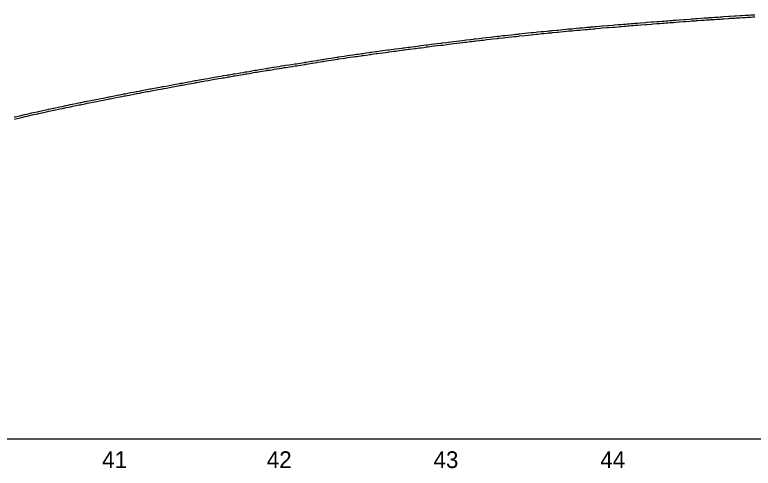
# Model space of a CAD drawing. Extents: x 2115752 to 2121174, y 562881 to 567245.
# Drawn here: x 2119738.2 to 2120180.3, y 566358.2 to 566630 of the extents above; entities that cross this region are included whole.
import ezdxf

# ---------------------------------------------------------------- set-up
doc = ezdxf.new("R2010")
doc.units = 0
for name, color, linetype in [('Exist Profile Cell', 7, 'Continuous'), ('Exist Vertical Profile Ground Line', 7, 'Continuous'), ('Exist Vertical Profile Horizontal Axis Label Major', 7, 'Continuous'), ('Scratch_Level_1', 7, 'Continuous')]:
    doc.layers.add(name, color=color, linetype=linetype)

msp = doc.modelspace()

# ---------------------------------------------------------------- linework, layer by layer
at = {"layer": 'Exist Profile Cell'}
msp.add_line((2116696.3, 566375.81), (2121174.42, 566375.81), dxfattribs=at)
at = {"layer": 'Exist Vertical Profile Ground Line'}
for points in [[(2120149.05, 566626.68), (2120150.9, 566626.82), (2120152.4, 566626.9), (2120153.55, 566626.98), (2120154.01, 566627.02), (2120154.64, 566627.07), (2120155.69, 566627.14), (2120157.12, 566627.22), (2120158.63, 566627.37), (2120159.06, 566627.39), (2120160.61, 566627.44), (2120161.62, 566627.53), (2120162.61, 566627.62), (2120165.77, 566627.83), (2120166.36, 566627.87), (2120169.24, 566628.05), (2120170.04, 566628.1), (2120172.31, 566628.24), (2120173.77, 566628.33), (2120175.64, 566628.44), (2120176.85, 566628.51), (2120177.46, 566628.54), (2120178.95, 566628.62), (2120180.06, 566628.67), (2120181.26, 566628.75)], [(2120011.63, 566614), (2120012.6, 566614.15), (2120013.46, 566614.26), (2120014.13, 566614.35), (2120016.38, 566614.59), (2120017.47, 566614.71), (2120018.78, 566614.85), (2120020.74, 566615.11), (2120022.89, 566615.36), (2120024.11, 566615.51), (2120027.23, 566615.86), (2120027.65, 566615.91), (2120028.14, 566615.95), (2120030.56, 566616.24), (2120031.93, 566616.4), (2120033.82, 566616.58), (2120035.74, 566616.78), (2120037.12, 566616.94), (2120038.3, 566617.06), (2120039.73, 566617.22), (2120040.35, 566617.28), (2120043.63, 566617.64), (2120045.58, 566617.85), (2120047.4, 566618.04), (2120048.98, 566618.17), (2120050.3, 566618.34), (2120051.33, 566618.44), (2120053.55, 566618.68), (2120055.02, 566618.82), (2120056.83, 566618.98), (2120057.78, 566619.07), (2120059.06, 566619.2), (2120059.64, 566619.23), (2120060.04, 566619.28), (2120062.87, 566619.57), (2120063.34, 566619.62), (2120066.63, 566619.94), (2120068.52, 566620.08), (2120069.9, 566620.27), (2120070.25, 566620.3), (2120070.67, 566620.34), (2120071.95, 566620.41), (2120073.16, 566620.57), (2120074.44, 566620.69), (2120076.45, 566620.86), (2120078.15, 566621.01), (2120079.73, 566621.14), (2120080.84, 566621.24), (2120082.08, 566621.36), (2120082.6, 566621.38), (2120083.03, 566621.43), (2120084.39, 566621.53), (2120085.48, 566621.65), (2120086.41, 566621.75), (2120088.42, 566621.94), (2120089.88, 566622.07), (2120093.09, 566622.33), (2120093.63, 566622.37), (2120096.24, 566622.57), (2120097.41, 566622.66), (2120099.58, 566622.84), (2120100.37, 566622.91), (2120100.71, 566622.94), (2120101.15, 566622.97), (2120102.76, 566623.08), (2120103.88, 566623.18), (2120105.16, 566623.28), (2120106.09, 566623.35), (2120107.4, 566623.46), (2120108.32, 566623.55), (2120109.48, 566623.66), (2120111.14, 566623.79), (2120112.98, 566623.93), (2120116.07, 566624.18), (2120116.66, 566624.23), (2120119.34, 566624.43), (2120120.41, 566624.51), (2120122.64, 566624.67), (2120123.55, 566624.74), (2120124.2, 566624.79), (2120125.93, 566624.92), (2120126.93, 566625.01), (2120127.98, 566625.08), (2120128.6, 566625.1), (2120129.15, 566625.17), (2120130.51, 566625.27), (2120131.17, 566625.33), (2120132.02, 566625.4), (2120132.64, 566625.44), (2120134, 566625.53), (2120135.97, 566625.74), (2120138.78, 566625.93), (2120139.18, 566625.96), (2120139.71, 566626), (2120142.5, 566626.21), (2120143.4, 566626.27), (2120144.6, 566626.32), (2120145.8, 566626.45), (2120146.4, 566626.49), (2120147.19, 566626.55), (2120149.05, 566626.68)], [(2119869.39, 566593.31), (2119870.01, 566593.41), (2119871.54, 566593.63), (2119873.3, 566594), (2119875.11, 566594.22), (2119876.49, 566594.51), (2119877.26, 566594.63), (2119878.63, 566594.82), (2119879.76, 566595.04), (2119881.2, 566595.32), (2119882.21, 566595.49), (2119883.11, 566595.65), (2119885.05, 566595.96), (2119886.4, 566596.17), (2119888.87, 566596.58), (2119889.26, 566596.64), (2119889.61, 566596.7), (2119891.05, 566596.88), (2119892.94, 566597.26), (2119893.45, 566597.34), (2119896.6, 566597.84), (2119898.1, 566598.05), (2119899.53, 566598.33), (2119900.51, 566598.48), (2119902.69, 566598.77), (2119904.29, 566599.02), (2119906.04, 566599.3), (2119907.01, 566599.43), (2119908.08, 566599.63), (2119909.29, 566599.82), (2119911.89, 566600.24), (2119912.25, 566600.3), (2119912.56, 566600.35), (2119914.12, 566600.57), (2119915.93, 566600.92), (2119916.45, 566601.01), (2119919.09, 566601.42), (2119919.73, 566601.52), (2119921.15, 566601.71), (2119922.37, 566601.94), (2119922.95, 566602.03), (2119923.66, 566602.16), (2119924.74, 566602.3), (2119925.74, 566602.48), (2119927.58, 566602.76), (2119928.92, 566602.97), (2119930, 566603.09), (2119931.28, 566603.33), (2119931.82, 566603.41), (2119932.24, 566603.48), (2119935.58, 566603.97), (2119937.66, 566604.28), (2119939.04, 566604.48), (2119940.7, 566604.68), (2119942.03, 566604.91), (2119943.01, 566605.06), (2119944.18, 566605.21), (2119945.32, 566605.4), (2119946.09, 566605.5), (2119946.95, 566605.63), (2119948.6, 566605.87), (2119950.67, 566606.16), (2119951.33, 566606.24), (2119951.87, 566606.32), (2119954.54, 566606.71), (2119955.11, 566606.79), (2119958.49, 566607.26), (2119961.65, 566607.67), (2119962.38, 566607.76), (2119965.09, 566608.12), (2119966.23, 566608.27), (2119968.25, 566608.54), (2119970.05, 566608.79), (2119970.87, 566608.88), (2119971.52, 566608.98), (2119974, 566609.32), (2119974.43, 566609.37), (2119974.78, 566609.42), (2119977.75, 566609.78), (2119978.16, 566609.83), (2119980.53, 566610.14), (2119981.52, 566610.26), (2119983.25, 566610.46), (2119984.62, 566610.68), (2119985.05, 566610.73), (2119985.5, 566610.79), (2119987.91, 566611.08), (2119989.46, 566611.28), (2119991.17, 566611.48), (2119993.19, 566611.72), (2119993.9, 566611.79), (2119994.46, 566611.87), (2119997.02, 566612.18), (2119997.77, 566612.28), (2120001.04, 566612.67), (2120004.66, 566613.12), (2120006.43, 566613.32), (2120007.63, 566613.51), (2120008.67, 566613.64), (2120010.9, 566613.91), (2120011.63, 566614)], [(2119738.06, 566567.51), (2119738.89, 566567.69), (2119742.2, 566568.45), (2119744.39, 566568.96), (2119745.64, 566569.25), (2119748.71, 566569.94), (2119749.53, 566570.12), (2119752.03, 566570.67), (2119752.68, 566570.81), (2119753.49, 566571.01), (2119754.55, 566571.22), (2119755.35, 566571.42), (2119757.27, 566571.86), (2119758.63, 566572.14), (2119759.84, 566572.38), (2119761.39, 566572.73), (2119761.83, 566572.82), (2119765.13, 566573.55), (2119766.79, 566573.86), (2119768.96, 566574.35), (2119770.44, 566574.62), (2119771.66, 566574.9), (2119772.85, 566575.17), (2119774.98, 566575.62), (2119775.71, 566575.75), (2119776.67, 566575.94), (2119777.58, 566576.09), (2119778.22, 566576.24), (2119780.41, 566576.69), (2119781.03, 566576.8), (2119781.57, 566576.92), (2119782.92, 566577.18), (2119784.82, 566577.6), (2119787.06, 566578.05), (2119788.18, 566578.27), (2119789.99, 566578.56), (2119791.37, 566578.87), (2119792.21, 566579.04), (2119794.64, 566579.51), (2119795.25, 566579.63), (2119796.04, 566579.8), (2119797.11, 566580), (2119797.96, 566580.18), (2119799.79, 566580.54), (2119801.2, 566580.82), (2119802.37, 566581.02), (2119803.79, 566581.33), (2119804.16, 566581.4), (2119804.47, 566581.46), (2119807.76, 566582.09), (2119809.47, 566582.37), (2119811.04, 566582.71), (2119811.44, 566582.79), (2119813, 566583.05), (2119814.32, 566583.32), (2119815.43, 566583.54), (2119817.49, 566583.93), (2119818.35, 566584.09), (2119819.31, 566584.28), (2119820.15, 566584.43), (2119820.87, 566584.57), (2119823.04, 566584.97), (2119824.11, 566585.18), (2119825.4, 566585.39), (2119826.81, 566585.69), (2119827.38, 566585.79), (2119828.97, 566586.06), (2119830.88, 566586.44), (2119833.84, 566586.98), (2119834.75, 566587.15), (2119837.2, 566587.6), (2119837.84, 566587.71), (2119838.59, 566587.86), (2119839.6, 566588.04), (2119840.47, 566588.21), (2119841.36, 566588.35), (2119842.52, 566588.59), (2119843.77, 566588.82), (2119846.28, 566589.27), (2119846.68, 566589.34), (2119847.01, 566589.4), (2119849.97, 566589.92), (2119850.36, 566589.99), (2119852.33, 566590.36), (2119853.89, 566590.64), (2119856.83, 566591.15), (2119857.9, 566591.33), (2119859.16, 566591.52), (2119860.12, 566591.71), (2119861.7, 566591.98), (2119862.66, 566592.13), (2119863.47, 566592.27), (2119865.54, 566592.64), (2119866.14, 566592.74), (2119866.72, 566592.84), (2119869.39, 566593.31)]]:
    msp.add_lwpolyline(points, dxfattribs=at)
at = {"layer": 'Scratch_Level_1'}
for points in [[(2120011.44, 566615.24), (2120012.43, 566615.39), (2120013.3, 566615.5), (2120013.98, 566615.59), (2120016.24, 566615.83), (2120017.33, 566615.95), (2120018.63, 566616.1), (2120020.59, 566616.35), (2120022.74, 566616.61), (2120023.97, 566616.75), (2120027.1, 566617.1), (2120027.52, 566617.15), (2120028.01, 566617.2), (2120030.41, 566617.48), (2120031.8, 566617.65), (2120033.69, 566617.83), (2120035.61, 566618.03), (2120036.98, 566618.18), (2120038.16, 566618.31), (2120039.6, 566618.46), (2120040.22, 566618.52), (2120043.5, 566618.88), (2120045.44, 566619.1), (2120047.29, 566619.29), (2120048.85, 566619.41), (2120050.15, 566619.58), (2120051.2, 566619.69), (2120053.43, 566619.92), (2120054.9, 566620.06), (2120056.71, 566620.22), (2120057.66, 566620.32), (2120058.97, 566620.44), (2120059.52, 566620.47), (2120059.89, 566620.52), (2120062.75, 566620.82), (2120063.23, 566620.86), (2120066.53, 566621.19), (2120068.39, 566621.32), (2120069.76, 566621.51), (2120070.13, 566621.55), (2120070.58, 566621.59), (2120071.83, 566621.66), (2120073.02, 566621.82), (2120074.33, 566621.93), (2120076.34, 566622.11), (2120078.04, 566622.26), (2120079.62, 566622.39), (2120080.72, 566622.49), (2120081.99, 566622.61), (2120082.5, 566622.63), (2120082.91, 566622.68), (2120084.28, 566622.78), (2120085.35, 566622.9), (2120086.29, 566622.99), (2120088.31, 566623.18), (2120089.77, 566623.31), (2120092.99, 566623.57), (2120093.54, 566623.62), (2120096.15, 566623.82), (2120097.31, 566623.91), (2120099.47, 566624.08), (2120100.27, 566624.16), (2120100.63, 566624.18), (2120101.07, 566624.21), (2120102.66, 566624.33), (2120103.77, 566624.42), (2120105.06, 566624.52), (2120105.99, 566624.6), (2120107.29, 566624.71), (2120108.2, 566624.8), (2120109.37, 566624.9), (2120111.04, 566625.04), (2120112.88, 566625.18), (2120115.97, 566625.43), (2120116.57, 566625.47), (2120119.25, 566625.68), (2120120.32, 566625.75), (2120122.54, 566625.92), (2120123.45, 566625.99), (2120124.11, 566626.04), (2120125.83, 566626.17), (2120126.83, 566626.25), (2120127.92, 566626.33), (2120128.51, 566626.35), (2120129.03, 566626.41), (2120130.41, 566626.52), (2120131.06, 566626.57), (2120131.93, 566626.64), (2120132.56, 566626.69), (2120133.9, 566626.77), (2120135.86, 566626.98), (2120138.69, 566627.18), (2120139.09, 566627.21), (2120139.62, 566627.24), (2120142.4, 566627.45), (2120143.33, 566627.52), (2120144.51, 566627.56), (2120145.69, 566627.7), (2120146.31, 566627.74), (2120147.1, 566627.8), (2120148.97, 566627.93)], [(2120148.96, 566627.93), (2120150.82, 566628.06), (2120152.32, 566628.15), (2120153.45, 566628.23), (2120153.9, 566628.26), (2120154.54, 566628.32), (2120155.61, 566628.39), (2120157.03, 566628.46), (2120158.53, 566628.61), (2120159, 566628.64), (2120160.53, 566628.69), (2120161.51, 566628.78), (2120162.51, 566628.87), (2120165.69, 566629.08), (2120166.28, 566629.12), (2120169.16, 566629.3), (2120169.96, 566629.35), (2120172.23, 566629.49), (2120173.7, 566629.58), (2120175.57, 566629.69), (2120176.79, 566629.75), (2120177.4, 566629.79), (2120178.88, 566629.86), (2120179.98, 566629.92), (2120181.21, 566630)], [(2119869.18, 566594.54), (2119869.82, 566594.65), (2119871.33, 566594.86), (2119873.09, 566595.23), (2119874.9, 566595.45), (2119876.26, 566595.74), (2119877.07, 566595.87), (2119878.43, 566596.05), (2119879.51, 566596.27), (2119880.98, 566596.56), (2119882, 566596.72), (2119882.9, 566596.88), (2119884.85, 566597.2), (2119886.2, 566597.4), (2119888.67, 566597.81), (2119889.07, 566597.87), (2119889.43, 566597.93), (2119890.85, 566598.12), (2119892.72, 566598.49), (2119893.26, 566598.58), (2119896.41, 566599.08), (2119897.89, 566599.29), (2119899.32, 566599.56), (2119900.34, 566599.71), (2119902.51, 566600.01), (2119904.09, 566600.26), (2119905.86, 566600.53), (2119906.81, 566600.66), (2119907.87, 566600.86), (2119909.09, 566601.05), (2119911.69, 566601.48), (2119912.05, 566601.54), (2119912.38, 566601.59), (2119913.91, 566601.8), (2119915.71, 566602.15), (2119916.25, 566602.24), (2119918.89, 566602.65), (2119919.55, 566602.76), (2119920.95, 566602.94), (2119922.16, 566603.17), (2119922.74, 566603.26), (2119923.46, 566603.39), (2119924.55, 566603.54), (2119925.54, 566603.71), (2119927.39, 566604), (2119928.76, 566604.21), (2119929.81, 566604.33), (2119931.08, 566604.56), (2119931.63, 566604.64), (2119932.05, 566604.71), (2119935.39, 566605.21), (2119937.48, 566605.52), (2119938.88, 566605.72), (2119940.52, 566605.92), (2119941.83, 566606.15), (2119942.84, 566606.3), (2119944, 566606.44), (2119945.14, 566606.64), (2119945.92, 566606.73), (2119946.77, 566606.87), (2119948.42, 566607.1), (2119950.51, 566607.4), (2119951.16, 566607.48), (2119951.69, 566607.56), (2119954.36, 566607.95), (2119954.94, 566608.03), (2119958.33, 566608.49), (2119961.49, 566608.91), (2119962.21, 566609), (2119964.92, 566609.36), (2119966.07, 566609.51), (2119968.08, 566609.78), (2119969.89, 566610.03), (2119970.71, 566610.12), (2119971.35, 566610.21), (2119973.84, 566610.55), (2119974.27, 566610.61), (2119974.62, 566610.66), (2119977.6, 566611.02), (2119978, 566611.07), (2119980.37, 566611.38), (2119981.36, 566611.51), (2119983.08, 566611.7), (2119984.46, 566611.92), (2119984.9, 566611.97), (2119985.35, 566612.03), (2119987.76, 566612.32), (2119989.31, 566612.52), (2119991.02, 566612.72), (2119993.05, 566612.96), (2119993.75, 566613.03), (2119994.3, 566613.11), (2119996.87, 566613.42), (2119997.62, 566613.52), (2120000.89, 566613.91), (2120004.51, 566614.37), (2120006.27, 566614.56), (2120007.45, 566614.75), (2120008.52, 566614.88), (2120010.74, 566615.15), (2120011.47, 566615.24)], [(2119737.78, 566568.73), (2119738.62, 566568.91), (2119741.92, 566569.67), (2119744.1, 566570.18), (2119745.37, 566570.47), (2119748.44, 566571.16), (2119749.26, 566571.34), (2119751.75, 566571.89), (2119752.4, 566572.03), (2119753.22, 566572.23), (2119754.27, 566572.44), (2119755.05, 566572.64), (2119757.01, 566573.08), (2119758.38, 566573.37), (2119759.58, 566573.6), (2119761.12, 566573.95), (2119761.57, 566574.05), (2119764.88, 566574.78), (2119766.54, 566575.09), (2119768.71, 566575.57), (2119770.18, 566575.84), (2119771.39, 566576.12), (2119772.59, 566576.39), (2119774.74, 566576.85), (2119775.48, 566576.98), (2119776.45, 566577.17), (2119777.34, 566577.32), (2119777.95, 566577.46), (2119780.18, 566577.92), (2119780.78, 566578.03), (2119781.32, 566578.15), (2119782.67, 566578.4), (2119784.56, 566578.83), (2119786.82, 566579.28), (2119787.96, 566579.5), (2119789.76, 566579.79), (2119791.11, 566580.09), (2119791.97, 566580.26), (2119794.41, 566580.74), (2119795, 566580.85), (2119795.79, 566581.03), (2119796.86, 566581.23), (2119797.7, 566581.41), (2119799.54, 566581.77), (2119800.97, 566582.05), (2119802.13, 566582.25), (2119803.54, 566582.56), (2119803.92, 566582.63), (2119804.23, 566582.69), (2119807.54, 566583.32), (2119809.23, 566583.6), (2119810.79, 566583.94), (2119811.22, 566584.02), (2119812.77, 566584.28), (2119814.08, 566584.55), (2119815.19, 566584.76), (2119817.26, 566585.16), (2119818.11, 566585.32), (2119819.08, 566585.51), (2119819.92, 566585.66), (2119820.64, 566585.8), (2119822.81, 566586.2), (2119823.89, 566586.41), (2119825.16, 566586.62), (2119826.57, 566586.92), (2119827.16, 566587.03), (2119828.75, 566587.29), (2119830.65, 566587.67), (2119833.61, 566588.2), (2119834.52, 566588.38), (2119836.99, 566588.83), (2119837.61, 566588.93), (2119838.35, 566589.09), (2119839.37, 566589.27), (2119840.25, 566589.44), (2119841.14, 566589.58), (2119842.27, 566589.82), (2119843.55, 566590.05), (2119846.05, 566590.5), (2119846.46, 566590.57), (2119846.79, 566590.63), (2119849.76, 566591.16), (2119850.14, 566591.22), (2119852.1, 566591.59), (2119853.68, 566591.87), (2119856.61, 566592.38), (2119857.7, 566592.57), (2119858.95, 566592.76), (2119859.9, 566592.94), (2119861.5, 566593.21), (2119862.46, 566593.36), (2119863.25, 566593.5), (2119865.32, 566593.87), (2119865.93, 566593.97), (2119866.51, 566594.07), (2119869.18, 566594.54)]]:
    msp.add_lwpolyline(points, dxfattribs=at)

# ---------------------------------------------------------------- texts
at = {"layer": 'Exist Vertical Profile Horizontal Axis Label Major'}
for s, p in [('41', (2119790.53, 566358.31)), ('42', (2119889.08, 566358.31)), ('43', (2119988.91, 566358.31)), ('44', (2120088.76, 566358.31))]:
    msp.add_text(s, height=10, dxfattribs=at).set_placement(p)

doc.saveas('drawing.dxf')
